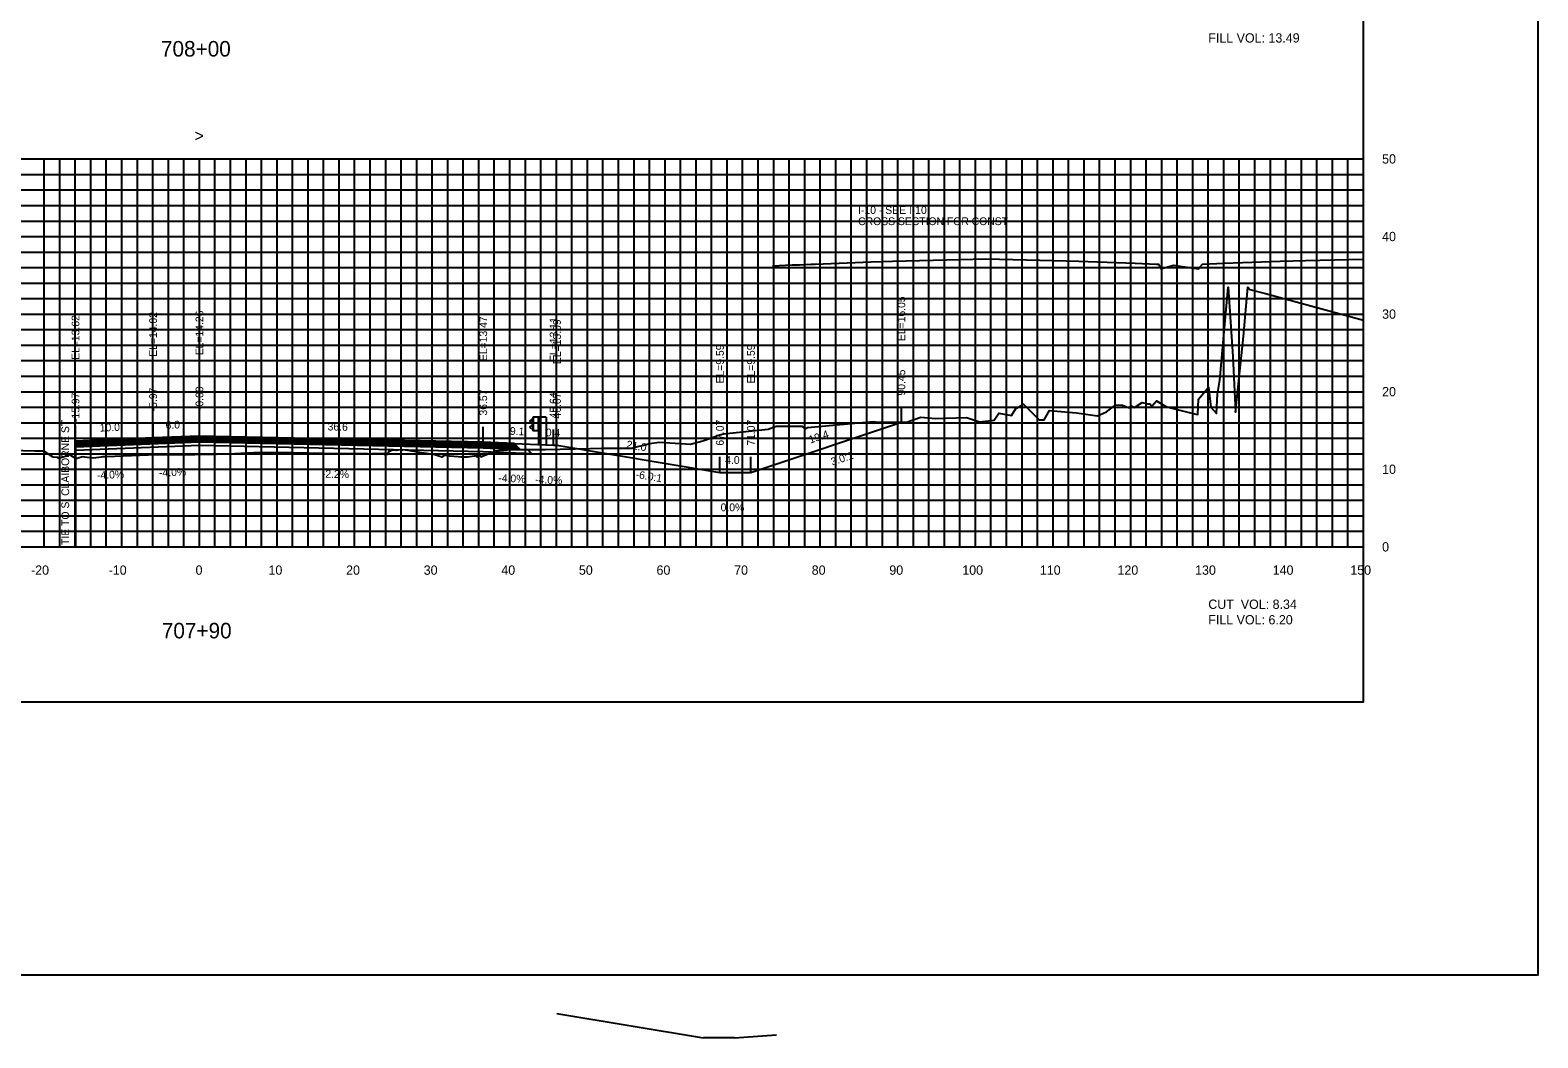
# Model space of a CAD drawing. Extents: x 1797518 to 1804843, y 248068 to 251132.
# Drawn here: x 1804649.2 to 1804843.5, y 250036.1 to 250166 of the extents above; entities that cross this region are included whole.
import ezdxf

# ---------------------------------------------------------------- set-up
doc = ezdxf.new("R2010")
doc.units = 0
for name, color, linetype in [('1', 7, 'Continuous'), ('10', 7, 'Continuous'), ('3', 7, 'Continuous'), ('31', 7, 'Continuous'), ('4', 7, 'Continuous'), ('60', 7, 'Continuous'), ('ANNO-TXT', 7, 'Continuous'), ('BASE', 7, 'Continuous'), ('CL-CNST', 7, 'Continuous'), ('Level 1', 7, 'Continuous'), ('Level 62', 7, 'Continuous'), ('LOWER BINDER', 7, 'Continuous'), ('M-ROADS', 7, 'Continuous'), ('UPPER BINDER', 7, 'Continuous'), ('WEARING', 7, 'Continuous')]:
    doc.layers.add(name, color=color, linetype=linetype)

msp = doc.modelspace()

# ---------------------------------------------------------------- linework, layer by layer
for p, q in [((1804761.45, 250115.48), (1804761.45, 250117.48)), ((1804655.03, 250113.06), (1804655.03, 250115.06)), ((1804665.03, 250113.46), (1804665.03, 250115.46)), ((1804671, 250113.69), (1804671, 250115.69)), ((1804707.57, 250112.9), (1804707.57, 250114.9)), ((1804716.64, 250112.54), (1804716.64, 250114.54)), ((1804717.07, 250112.52), (1804717.07, 250114.52)), ((1804738.07, 250109.02), (1804738.07, 250111.02)), ((1804742.07, 250109.02), (1804742.07, 250111.02))]:
    msp.add_line(p, q)
msp.add_lwpolyline([(1804521, 250079.43), (1804821, 250079.43), (1804821, 250269.43), (1804521, 250269.43)], close=True)
at = {"layer": '1'}
for p, q in [((1804717.07, 250039.28), (1804735.94, 250036.13)), ((1804739.94, 250036.13), (1804735.94, 250036.13)), ((1804739.94, 250036.13), (1804745.34, 250036.53))]:
    msp.add_line(p, q, dxfattribs=at)
msp.add_lwpolyline([(1804501.93, 250290.86), (1804843.47, 250290.86), (1804843.47, 250044.2), (1804501.93, 250044.2)], close=True, dxfattribs=at)
at = {"layer": '3'}
msp.add_line((1804655.03, 250113.06), (1804655.03, 250099.43), dxfattribs=at)
at = {"layer": '60'}
for p, q in [((1804821, 250099.43), (1804821, 250149.43)), ((1804821.06, 250149.43), (1804821, 250149.43)), ((1804821.06, 250139.43), (1804821, 250139.43)), ((1804821.06, 250129.43), (1804821, 250129.43)), ((1804821.06, 250119.43), (1804821, 250119.43)), ((1804821.06, 250109.43), (1804821, 250109.43)), ((1804521, 250099.43), (1804821, 250099.43)), ((1804651, 250099.37), (1804651, 250099.43)), ((1804661, 250099.37), (1804661, 250099.43)), ((1804671, 250099.37), (1804671, 250099.43)), ((1804681, 250099.37), (1804681, 250099.43)), ((1804691, 250099.37), (1804691, 250099.43)), ((1804701, 250099.37), (1804701, 250099.43)), ((1804711, 250099.37), (1804711, 250099.43)), ((1804721, 250099.37), (1804721, 250099.43)), ((1804731, 250099.37), (1804731, 250099.43)), ((1804741, 250099.37), (1804741, 250099.43)), ((1804751, 250099.37), (1804751, 250099.43)), ((1804761, 250099.37), (1804761, 250099.43)), ((1804771, 250099.37), (1804771, 250099.43)), ((1804781, 250099.37), (1804781, 250099.43)), ((1804791, 250099.37), (1804791, 250099.43)), ((1804801, 250099.37), (1804801, 250099.43)), ((1804811, 250099.37), (1804811, 250099.43)), ((1804821, 250099.37), (1804821, 250099.43)), ((1804821.06, 250099.43), (1804821, 250099.43))]:
    msp.add_line(p, q, dxfattribs=at)
at = {"layer": 'BASE'}
msp.add_lwpolyline([(1804655.03, 250112.34), (1804671, 250112.97), (1804707.57, 250112.18), (1804712.32, 250111.99), (1804713.32, 250111.95), (1804713.84, 250111.43), (1804707.57, 250111.68), (1804671, 250112.47), (1804655.03, 250111.84)], close=True, dxfattribs=at)
at = {"layer": 'CL-CNST'}
for points in [[(1804744.83, 250135.65), (1804747.37, 250135.76), (1804748.33, 250135.79), (1804749.78, 250135.85), (1804750.33, 250135.87), (1804757.58, 250136.16), (1804760.33, 250136.27), (1804769.04, 250136.47), (1804772.33, 250136.54), (1804781.04, 250136.35), (1804784.33, 250136.27), (1804791.59, 250135.98), (1804794.33, 250135.87), (1804794.51, 250135.87), (1804794.58, 250135.86), (1804794.79, 250135.43), (1804794.87, 250135.26), (1804796.11, 250135.6), (1804796.58, 250135.73), (1804797.36, 250135.6), (1804799.72, 250135.26), (1804799.86, 250135.43), (1804800.26, 250135.87), (1804802.99, 250135.98), (1804810.26, 250136.27), (1804813.54, 250136.35), (1804821, 250136.51)], [(1804655.03, 250113.06), (1804665.03, 250113.46), (1804671, 250113.69), (1804707.57, 250112.9), (1804716.64, 250112.54), (1804717.07, 250112.52), (1804738.07, 250109.02), (1804742.07, 250109.02), (1804761.45, 250115.48)]]:
    msp.add_lwpolyline(points, dxfattribs=at)
at = {"layer": 'Level 1'}
for p, q in [((1804713.95, 250115.99), (1804713.58, 250115.69)), ((1804713.58, 250115.62), (1804713.95, 250115.34)), ((1804713.95, 250115.2), (1804713.58, 250114.9)), ((1804713.58, 250114.83), (1804713.95, 250114.54)), ((1804713.95, 250116.14), (1804713.95, 250114.39)), ((1804715.7, 250116.14), (1804713.95, 250116.14)), ((1804714, 250116.14), (1804714, 250114.39)), ((1804714.65, 250116.14), (1804714.65, 250114.39)), ((1804714.7, 250116.14), (1804714.7, 250112.62)), ((1804715.7, 250116.14), (1804715.7, 250112.58)), ((1804714.7, 250114.39), (1804713.95, 250114.39))]:
    msp.add_line(p, q, dxfattribs=at)
for centre in [(1804713.62, 250115.66), (1804713.62, 250114.86)]:
    msp.add_arc(centre, 0.05, 135, 226.6208, dxfattribs=at)
at = {"layer": 'Level 62'}
for p, q in [((1804521, 250149.43), (1804821, 250149.43)), ((1804651, 250099.43), (1804651, 250149.43)), ((1804653, 250099.43), (1804653, 250149.43)), ((1804655, 250099.43), (1804655, 250149.43)), ((1804657, 250099.43), (1804657, 250149.43)), ((1804659, 250099.43), (1804659, 250149.43)), ((1804661, 250099.43), (1804661, 250149.43)), ((1804663, 250099.43), (1804663, 250149.43)), ((1804665, 250099.43), (1804665, 250149.43)), ((1804667, 250099.43), (1804667, 250149.43)), ((1804669, 250099.43), (1804669, 250149.43)), ((1804671, 250099.43), (1804671, 250149.43)), ((1804673, 250099.43), (1804673, 250149.43)), ((1804675, 250099.43), (1804675, 250149.43)), ((1804677, 250099.43), (1804677, 250149.43)), ((1804679, 250099.43), (1804679, 250149.43)), ((1804681, 250099.43), (1804681, 250149.43)), ((1804683, 250099.43), (1804683, 250149.43)), ((1804685, 250099.43), (1804685, 250149.43)), ((1804687, 250099.43), (1804687, 250149.43)), ((1804689, 250099.43), (1804689, 250149.43)), ((1804691, 250099.43), (1804691, 250149.43)), ((1804693, 250099.43), (1804693, 250149.43)), ((1804695, 250099.43), (1804695, 250149.43)), ((1804697, 250099.43), (1804697, 250149.43)), ((1804699, 250099.43), (1804699, 250149.43)), ((1804701, 250099.43), (1804701, 250149.43)), ((1804703, 250099.43), (1804703, 250149.43)), ((1804705, 250099.43), (1804705, 250149.43)), ((1804707, 250099.43), (1804707, 250149.43)), ((1804709, 250099.43), (1804709, 250149.43)), ((1804711, 250099.43), (1804711, 250149.43)), ((1804713, 250099.43), (1804713, 250149.43)), ((1804715, 250099.43), (1804715, 250149.43)), ((1804717, 250099.43), (1804717, 250149.43)), ((1804719, 250099.43), (1804719, 250149.43)), ((1804721, 250099.43), (1804721, 250149.43)), ((1804723, 250099.43), (1804723, 250149.43)), ((1804725, 250099.43), (1804725, 250149.43)), ((1804727, 250099.43), (1804727, 250149.43)), ((1804729, 250099.43), (1804729, 250149.43)), ((1804731, 250099.43), (1804731, 250149.43)), ((1804733, 250099.43), (1804733, 250149.43)), ((1804735, 250099.43), (1804735, 250149.43)), ((1804737, 250099.43), (1804737, 250149.43)), ((1804739, 250099.43), (1804739, 250149.43)), ((1804741, 250099.43), (1804741, 250149.43)), ((1804743, 250099.43), (1804743, 250149.43)), ((1804745, 250099.43), (1804745, 250149.43)), ((1804747, 250099.43), (1804747, 250149.43)), ((1804749, 250099.43), (1804749, 250149.43)), ((1804751, 250099.43), (1804751, 250149.43)), ((1804753, 250099.43), (1804753, 250149.43)), ((1804755, 250099.43), (1804755, 250149.43)), ((1804757, 250099.43), (1804757, 250149.43)), ((1804759, 250099.43), (1804759, 250149.43)), ((1804761, 250099.43), (1804761, 250149.43)), ((1804763, 250099.43), (1804763, 250149.43)), ((1804765, 250099.43), (1804765, 250149.43)), ((1804767, 250099.43), (1804767, 250149.43)), ((1804769, 250099.43), (1804769, 250149.43)), ((1804771, 250099.43), (1804771, 250149.43)), ((1804773, 250099.43), (1804773, 250149.43)), ((1804775, 250099.43), (1804775, 250149.43)), ((1804777, 250099.43), (1804777, 250149.43)), ((1804779, 250099.43), (1804779, 250149.43)), ((1804781, 250099.43), (1804781, 250149.43)), ((1804783, 250099.43), (1804783, 250149.43)), ((1804785, 250099.43), (1804785, 250149.43)), ((1804787, 250099.43), (1804787, 250149.43)), ((1804789, 250099.43), (1804789, 250149.43)), ((1804791, 250099.43), (1804791, 250149.43)), ((1804793, 250099.43), (1804793, 250149.43)), ((1804795, 250099.43), (1804795, 250149.43)), ((1804797, 250099.43), (1804797, 250149.43)), ((1804799, 250099.43), (1804799, 250149.43)), ((1804801, 250099.43), (1804801, 250149.43)), ((1804803, 250099.43), (1804803, 250149.43)), ((1804805, 250099.43), (1804805, 250149.43)), ((1804807, 250099.43), (1804807, 250149.43)), ((1804809, 250099.43), (1804809, 250149.43)), ((1804811, 250099.43), (1804811, 250149.43)), ((1804813, 250099.43), (1804813, 250149.43)), ((1804815, 250099.43), (1804815, 250149.43)), ((1804817, 250099.43), (1804817, 250149.43)), ((1804819, 250099.43), (1804819, 250149.43)), ((1804821, 250099.43), (1804821, 250149.43)), ((1804521, 250147.43), (1804821, 250147.43)), ((1804521, 250145.43), (1804821, 250145.43)), ((1804521, 250143.43), (1804821, 250143.43)), ((1804521, 250141.43), (1804821, 250141.43)), ((1804521, 250139.43), (1804821, 250139.43)), ((1804521, 250137.43), (1804821, 250137.43)), ((1804521, 250135.43), (1804821, 250135.43)), ((1804521, 250133.43), (1804821, 250133.43)), ((1804521, 250131.43), (1804821, 250131.43)), ((1804521, 250129.43), (1804821, 250129.43)), ((1804521, 250127.43), (1804821, 250127.43)), ((1804521, 250125.43), (1804821, 250125.43)), ((1804521, 250123.43), (1804821, 250123.43)), ((1804521, 250121.43), (1804821, 250121.43)), ((1804521, 250119.43), (1804821, 250119.43)), ((1804521, 250117.43), (1804821, 250117.43)), ((1804521, 250115.43), (1804821, 250115.43)), ((1804521, 250113.43), (1804821, 250113.43)), ((1804521, 250111.43), (1804821, 250111.43)), ((1804521, 250109.43), (1804821, 250109.43)), ((1804521, 250107.43), (1804821, 250107.43)), ((1804521, 250105.43), (1804821, 250105.43)), ((1804521, 250103.43), (1804821, 250103.43)), ((1804521, 250101.43), (1804821, 250101.43)), ((1804521, 250099.43), (1804821, 250099.43))]:
    msp.add_line(p, q, dxfattribs=at)
at = {"layer": 'LOWER BINDER'}
for points in [[(1804671, 250113.35), (1804707.57, 250112.56), (1804711.92, 250112.39), (1804712.12, 250112.19), (1804707.57, 250112.37), (1804671, 250113.16), (1804655.03, 250112.53), (1804655.03, 250112.72)], [(1804671, 250113.16), (1804707.57, 250112.37), (1804712.12, 250112.19), (1804712.32, 250111.99), (1804707.57, 250112.18), (1804671, 250112.97), (1804655.03, 250112.34), (1804655.03, 250112.53)]]:
    msp.add_lwpolyline(points, close=True, dxfattribs=at)
at = {"layer": 'M-ROADS'}
msp.add_lwpolyline([(1804645.07, 250111.93), (1804649.78, 250111.81), (1804650.05, 250111.82), (1804650.91, 250111.81), (1804652.11, 250111.03), (1804652.65, 250110.98), (1804652.89, 250110.87), (1804653.59, 250111.06), (1804653.88, 250111.17), (1804654.08, 250111.23), (1804654.15, 250111.26), (1804654.19, 250111.29), (1804654.21, 250111.29), (1804654.22, 250111.3), (1804654.23, 250111.31), (1804654.24, 250111.31), (1804654.25, 250111.31), (1804654.25, 250111.31), (1804654.25, 250111.32), (1804654.26, 250111.32), (1804654.28, 250111.33), (1804654.29, 250111.33), (1804654.29, 250111.34), (1804654.29, 250111.33), (1804654.3, 250111.31), (1804654.3, 250111.41), (1804654.4, 250111.25), (1804655.03, 250110.86), (1804655.06, 250110.87), (1804655.06, 250110.87), (1804655.06, 250110.87), (1804655.06, 250110.87), (1804655.07, 250110.87), (1804655.07, 250110.87), (1804655.09, 250110.87), (1804655.19, 250110.82), (1804655.21, 250110.82), (1804655.24, 250110.84), (1804655.39, 250110.88), (1804655.93, 250111.06), (1804656.19, 250111.04), (1804656.86, 250110.94), (1804657.31, 250110.89), (1804658.4, 250111.02), (1804658.56, 250111.06), (1804659.03, 250111.08), (1804665.45, 250111.33), (1804666.41, 250111.35), (1804667.89, 250111.33), (1804667.93, 250111.33), (1804668.18, 250111.33), (1804669.61, 250111.32), (1804670.4, 250111.34), (1804673.21, 250111.39), (1804674.2, 250111.41), (1804674.36, 250111.41), (1804674.48, 250111.41), (1804674.65, 250111.42), (1804678.03, 250111.58), (1804678.84, 250111.59), (1804680.37, 250111.58), (1804680.5, 250111.58), (1804680.51, 250111.58), (1804682.05, 250111.58), (1804682.97, 250111.59), (1804689.14, 250111.48), (1804689.91, 250111.46), (1804690.03, 250111.46), (1804690.24, 250111.46), (1804692.32, 250111.46), (1804692.61, 250111.45), (1804692.68, 250111.42), (1804693.23, 250111.45), (1804694.86, 250111.46), (1804694.87, 250111.38), (1804694.88, 250111.42), (1804694.88, 250111.37), (1804694.89, 250111.35), (1804694.91, 250111.42), (1804694.93, 250111.26), (1804694.94, 250111.27), (1804694.94, 250111.27), (1804694.95, 250111.31), (1804694.95, 250111.42), (1804694.97, 250111.58), (1804695.2, 250111.32), (1804695.23, 250111.39), (1804695.24, 250111.34), (1804695.51, 250111.82), (1804695.65, 250111.82), (1804695.65, 250111.86), (1804695.8, 250111.87), (1804695.96, 250111.93), (1804696.08, 250111.95), (1804696.28, 250111.95), (1804696.37, 250111.9), (1804697, 250111.97), (1804697.09, 250111.87), (1804697.27, 250111.97), (1804701.35, 250111.34), (1804702.25, 250111.05), (1804702.31, 250111.05), (1804702.34, 250111.06), (1804702.66, 250111.3), (1804702.7, 250111.24), (1804703.24, 250111.15), (1804704.33, 250111.06), (1804704.69, 250111.05), (1804704.82, 250111.05), (1804705.11, 250111.04), (1804705.54, 250111.04), (1804706.46, 250111.16), (1804706.55, 250111.2), (1804706.58, 250111.31), (1804706.61, 250111.22), (1804706.73, 250111.03), (1804706.83, 250111.06), (1804707, 250111.56), (1804707.25, 250111.05), (1804709.15, 250111.79), (1804711.23, 250111.97), (1804712.15, 250111.97), (1804715.56, 250111.96), (1804721.37, 250112.11), (1804722.82, 250112.16), (1804723.85, 250112.13), (1804725.51, 250112.13), (1804726.71, 250112.16), (1804727.26, 250112.3), (1804728.26, 250112.53), (1804729.01, 250112.74), (1804730.22, 250112.9), (1804732.29, 250112.78), (1804734.26, 250112.67), (1804735.88, 250113.1), (1804737.13, 250113.52), (1804737.77, 250113.76), (1804738.54, 250114), (1804743.02, 250114.48), (1804744.3, 250114.59), (1804745.3, 250114.99), (1804746.72, 250114.99), (1804748.62, 250114.99), (1804749.1, 250114.7), (1804749.36, 250114.82), (1804754.49, 250115.28), (1804757.87, 250115.59), (1804758.44, 250115.48), (1804760.54, 250115.48), (1804762.12, 250115.48), (1804763.98, 250116.15), (1804765.87, 250115.96), (1804769.85, 250116.09), (1804771.53, 250115.53), (1804772.3, 250115.62), (1804773.42, 250115.76), (1804774, 250116.66), (1804775.63, 250116.34), (1804776.19, 250117.28), (1804777.21, 250117.81), (1804778.19, 250116.83), (1804779.2, 250115.81), (1804779.86, 250115.81), (1804780.54, 250117.01), (1804784.03, 250116.69), (1804786.72, 250116.3), (1804787.88, 250116.85), (1804789.09, 250117.72), (1804789.96, 250117.71), (1804790.81, 250117.35), (1804791.03, 250117.65), (1804791.49, 250117.4), (1804792.48, 250118.04), (1804793.2, 250117.86), (1804793.47, 250117.88), (1804793.71, 250117.57), (1804794.33, 250118.26), (1804795.61, 250117.49), (1804799.41, 250116.51), (1804799.65, 250116.5), (1804799.74, 250118.45), (1804801.03, 250120.01), (1804801.32, 250117.44), (1804802.05, 250116.63), (1804802.19, 250119.12), (1804802.5, 250120.91), (1804803.55, 250132.89), (1804804.15, 250123.98), (1804804.52, 250116.79), (1804805.54, 250126.56), (1804806.09, 250132.88), (1804806.37, 250132.59), (1804808.37, 250132.09), (1804821, 250128.63)], dxfattribs=at)
at = {"layer": 'UPPER BINDER'}
msp.add_lwpolyline([(1804711.92, 250112.39), (1804711.72, 250112.59), (1804707.57, 250112.75), (1804671, 250113.54), (1804655.03, 250112.91), (1804655.03, 250112.72), (1804671, 250113.35), (1804707.57, 250112.56)], close=True, dxfattribs=at)
at = {"layer": 'WEARING'}
msp.add_lwpolyline([(1804711.72, 250112.59), (1804711.57, 250112.74), (1804707.57, 250112.9), (1804671, 250113.69), (1804665.03, 250113.46), (1804655.03, 250113.06), (1804655.03, 250112.91), (1804671, 250113.54), (1804707.57, 250112.75)], close=True, dxfattribs=at)

# ---------------------------------------------------------------- texts
for s, rotation, p in [('3.0:1', 18.4349, (1804752.55, 250109.88)), ('-6.0:1', 350.5377, (1804727.16, 250108.31))]:
    msp.add_text(s, height=1, rotation=rotation).set_placement(p)
at = {"layer": '1'}
for s, p in [('708+00', (1804666.04, 250162.63)), ('707+90', (1804666.15, 250087.63))]:
    msp.add_text(s, height=2, dxfattribs=at).set_placement(p)
at = {"layer": '10'}
for s, p in [('-20', (1804649.3, 250095.83)), ('-10', (1804659.3, 250095.83)), ('0', (1804670.5, 250095.83)), ('10', (1804679.9, 250095.83)), ('20', (1804689.9, 250095.83)), ('30', (1804699.9, 250095.83)), ('40', (1804709.9, 250095.83)), ('50', (1804719.9, 250095.83)), ('60', (1804729.9, 250095.83)), ('70', (1804739.9, 250095.83)), ('80', (1804749.9, 250095.83)), ('90', (1804759.9, 250095.83)), ('100', (1804769.3, 250095.83)), ('110', (1804779.3, 250095.83)), ('120', (1804789.3, 250095.83)), ('130', (1804799.3, 250095.83)), ('140', (1804809.3, 250095.83)), ('150', (1804819.3, 250095.83))]:
    msp.add_text(s, height=1.2, dxfattribs=at).set_placement(p)
at = {"layer": '3'}
for s, p in [('CROSS SECTION FOR CONST ', (1804755.88, 250140.9)), ('I-10 - SEE I-10', (1804755.88, 250142.34))]:
    msp.add_text(s, height=1, dxfattribs=at).set_placement(p)
for s, p in [('EL=16.05', (1804761.95, 250125.95)), ('EL=13.62', (1804655.53, 250123.53)), ('EL=14.02', (1804665.53, 250123.93)), ('EL=14.26', (1804671.5, 250124.12)), ('EL=13.47', (1804708.07, 250123.37)), ('EL=13.11', (1804717.14, 250123.26)), ('EL=13.09', (1804717.57, 250122.99)), ('EL=9.59', (1804738.57, 250120.49)), ('EL=9.59', (1804742.57, 250120.49)), ('90.45', (1804761.95, 250118.93)), ('-15.97', (1804655.53, 250115.51)), ('-5.97', (1804665.53, 250116.9)), ('-0.00', (1804671.5, 250117.06)), ('36.57', (1804708.07, 250116.35)), ('45.64', (1804717.14, 250115.99)), ('46.07', (1804717.57, 250115.97)), ('TIE TO S. CLAIBORNE ST', (1804654.21, 250099.68)), ('67.07', (1804738.57, 250112.47)), ('71.07', (1804742.57, 250112.47))]:
    msp.add_text(s, height=1, rotation=90, dxfattribs=at).set_placement(p)
at = {"layer": '31'}
for s, p in [('50', (1804823.4, 250148.83)), ('40', (1804823.4, 250138.83)), ('30', (1804823.4, 250128.83)), ('20', (1804823.4, 250118.83)), ('10', (1804823.4, 250108.83)), ('0', (1804823.4, 250098.83))]:
    msp.add_text(s, height=1.2, dxfattribs=at).set_placement(p)
at = {"layer": '4'}
for s, rotation, p in [('10.0', 2.2906, (1804658.17, 250114.28)), ('6.0', 2.2906, (1804666.65, 250114.62)), ('36.6', 358.758, (1804687.51, 250114.44)), ('9.1', 357.7094, (1804710.99, 250113.87)), ('0.4', 357.7094, (1804715.62, 250113.68)), ('21.0', 350.5377, (1804725.96, 250112.16)), ('19.4', 18.4349, (1804749.72, 250112.73)), ('-4.0%', 2.2906, (1804657.82, 250108.16)), ('-4.0%', 2.2906, (1804665.81, 250108.48)), ('-2.2%', 358.758, (1804686.77, 250108.35)), ('-4.0%', 357.7094, (1804709.5, 250107.82)), ('-4.0%', 357.7094, (1804714.25, 250107.63))]:
    msp.add_text(s, height=1, rotation=rotation, dxfattribs=at).set_placement(p)
for s, p in [('4.0', (1804738.75, 250110.12)), ('0.0%', (1804738.16, 250104.02))]:
    msp.add_text(s, height=1, dxfattribs=at).set_placement(p)
at = {"layer": '60'}
msp.add_text('>', height=1.5, dxfattribs=at).set_placement((1804670.39, 250151.68))
at = {"layer": 'ANNO-TXT'}
for s, p in [('FILL VOL: 13.49', (1804801, 250164.43)), ('CUT  VOL: 8.34', (1804801, 250091.43)), ('FILL VOL: 6.20', (1804801, 250089.43))]:
    msp.add_text(s, height=1.2, dxfattribs=at).set_placement(p)

doc.saveas('drawing.dxf')
